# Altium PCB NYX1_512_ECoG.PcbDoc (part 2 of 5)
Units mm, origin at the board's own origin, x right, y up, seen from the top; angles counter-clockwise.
Board outline 46.64 x 13 mm, 4 copper layers (metal 2, via, metal1, electrodes), stack 0.007 mm thick; 9 components, 547 nets, 1871 pads, 0 vias.
Unrouted connection lines stored in the file: 652.
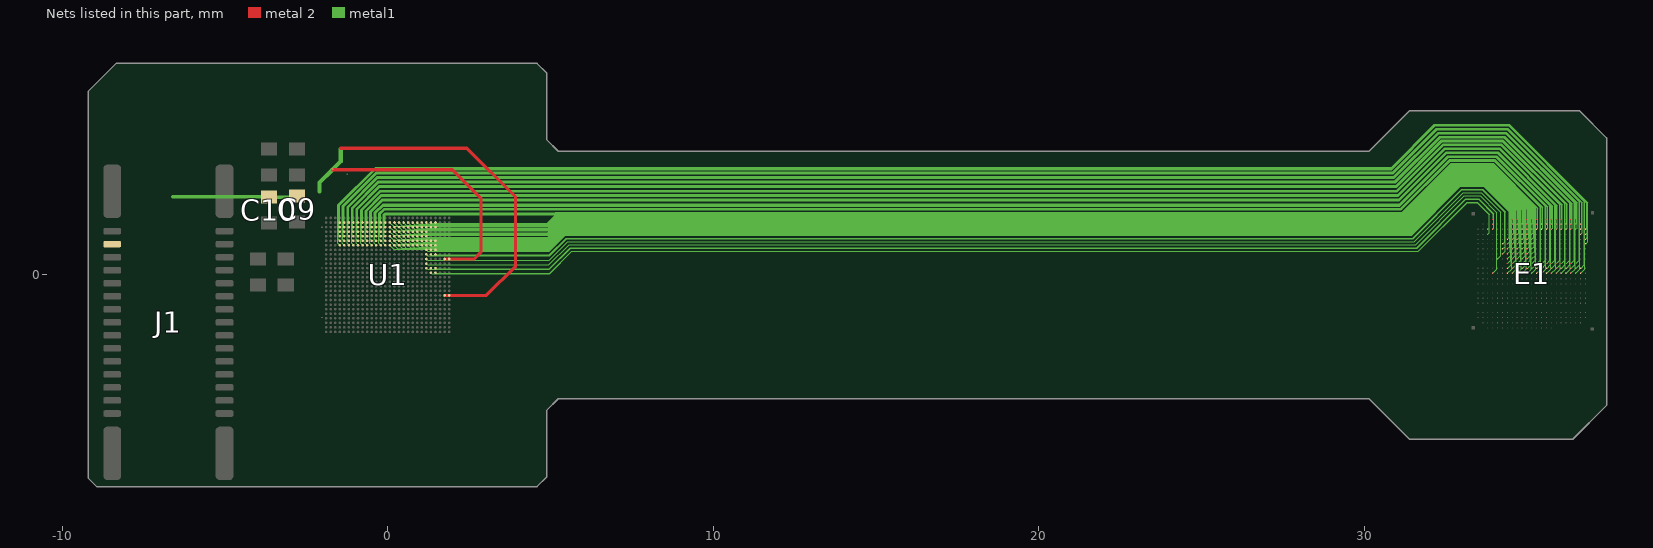
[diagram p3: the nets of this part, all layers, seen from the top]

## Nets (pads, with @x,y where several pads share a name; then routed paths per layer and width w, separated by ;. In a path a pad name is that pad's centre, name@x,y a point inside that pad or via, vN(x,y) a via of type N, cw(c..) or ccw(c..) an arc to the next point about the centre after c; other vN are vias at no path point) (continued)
DVSS_BOT: C9.2 C10.2 J1.3 pad.34@-1.423,3.873 pad.34@-1.423,3.891 pad.34@-1.423,3.909 pad.34@-1.441,3.873 pad.34@-1.441,3.891 pad.34@-1.441,3.909 pad.34@-1.459,3.873 pad.34@-1.459,3.891 pad.34@-1.459,3.909 pad.34@-1.679,3.217 pad.34@-1.679,3.235 pad.34@-1.679,3.253 pad.34@-1.697,3.217 pad.34@-1.697,3.235 pad.34@-1.697,3.253 pad.34@-1.715,3.217 pad.34@-1.715,3.235 pad.34@-1.715,3.253 U1.A10 U1.A18 U1.B10 U1.B18 | length 23.9
  metal 2 w0.1: pad.34@-1.697,3.235 pad.34@-1.679,3.235 1.99,3.235 2.866,2.359 2.866,0.696 2.661,0.491 U1.B10@1.75,0.491 ; pad.34@-1.441,3.891 pad.34@-1.423,3.891 2.433,3.891 3.929,2.395 3.929,0.264 3.036,-0.629 U1.A18@1.89,-0.629 U1.B18@1.75,-0.629
  metal1 w0.08: pad.34@-1.715,3.217 pad.34@-1.697,3.235 ; pad.34@-1.441,3.873 pad.34@-1.441,3.891
  metal1 w0.1: -6.602,2.399 -3.651,2.399 C10.2@-3.644,2.392 ; C10.2@-3.643,2.384 C9.2@-2.853,2.384 ; C9.2@-2.814,2.411 C9.2@-2.786,2.411 ; C9.2@-2.786,2.421 C9.2@-2.732,2.421 ; -2.106,2.546 -2.087,2.566
  metal1 w0.127: -2.087,2.566 -2.087,2.845 pad.34@-1.715,3.217 ; pad.34@-1.697,3.235 -1.441,3.491 pad.34@-1.441,3.873
el0: E1.190 pad.34@35.141,0.514 U1.D2 | length 36.7
  metal 2 w0.012: E1.190@35.141,0.494 pad.34@35.141,0.514
  metal1 w0.005: U1.D2@1.47,1.611 1.487,1.594 4.91,1.594 5.183,1.866 30.141,1.866 31.19,1.866 32.69,3.366 33.935,3.366 35.241,2.06 35.241,0.594 35.16,0.514 pad.34@35.141,0.514
el1: E1.212 pad.34@34.991,0.364 U1.D3 | length 36.6
  metal 2 w0.012: E1.212@34.991,0.344 pad.34@34.991,0.364
  metal1 w0.005: U1.D3@1.47,1.471 1.487,1.454 4.927,1.454 5.23,1.756 30.141,1.756 31.236,1.756 32.736,3.256 33.889,3.256 35.101,2.045 35.101,0.454 35.01,0.364 pad.34@34.991,0.364
el2: E1.95 pad.34@34.691,1.114 U1.D6 | length 35.4
  metal 2 w0.012: E1.95@34.691,1.094 pad.34@34.691,1.114
  metal1 w0.005: U1.D6@1.47,1.051 1.487,1.034 4.922,1.034 5.351,1.463 30.141,1.463 31.352,1.463 32.852,2.963 33.773,2.963 34.751,1.985 34.751,1.154 34.71,1.114 pad.34@34.691,1.114
el3: E1.117 pad.34@34.541,0.964 U1.D7 | length 35.4
  metal 2 w0.012: E1.117@34.541,0.944 pad.34@34.541,0.964
  metal1 w0.005: U1.D7@1.47,0.911 1.487,0.894 4.938,0.894 5.397,1.353 30.141,1.353 31.398,1.353 32.898,2.853 33.727,2.853 34.611,1.969 34.611,1.014 34.56,0.964 pad.34@34.541,0.964
el4: E1.167 pad.34@35.141,0.664 U1.E2 | length 36.6
  metal 2 w0.012: E1.167@35.141,0.644 pad.34@35.141,0.664
  metal1 w0.005: U1.E2@1.33,1.611 1.357,1.584 4.915,1.584 5.187,1.856 30.141,1.856 31.194,1.856 32.694,3.356 33.931,3.356 35.231,2.056 35.231,0.734 35.16,0.664 pad.34@35.141,0.664
el5: E1.189 pad.34@34.991,0.514 U1.E3 | length 36.6
  metal 2 w0.012: E1.189@34.991,0.494 pad.34@34.991,0.514
  metal1 w0.005: U1.E3@1.33,1.471 1.357,1.444 4.932,1.444 5.234,1.746 30.141,1.746 31.24,1.746 32.74,3.246 33.885,3.246 35.091,2.041 35.091,0.594 35.01,0.514 pad.34@34.991,0.514
el6: E1.72 pad.34@34.691,1.264 U1.E6 | length 35.4
  metal 2 w0.012: E1.72@34.691,1.244 pad.34@34.691,1.264
  metal1 w0.005: U1.E6@1.33,1.051 1.357,1.024 4.926,1.024 5.355,1.453 30.141,1.453 31.356,1.453 32.856,2.953 33.768,2.953 34.741,1.98 34.741,1.294 34.71,1.264 pad.34@34.691,1.264
el7: E1.94 pad.34@34.541,1.114 U1.E7 | length 35.4
  metal 2 w0.012: E1.94@34.541,1.094 pad.34@34.541,1.114
  metal1 w0.005: U1.E7@1.33,0.911 1.357,0.884 4.943,0.884 5.401,1.343 30.141,1.343 31.402,1.343 32.902,2.843 33.723,2.843 34.601,1.965 34.601,1.154 34.56,1.114 pad.34@34.541,1.114
el8: E1.144 pad.34@35.141,0.814 U1.F2 | length 36.6
  metal 2 w0.012: E1.144@35.141,0.794 pad.34@35.141,0.814
  metal1 w0.005: U1.F2@1.19,1.611 1.227,1.574 4.919,1.574 5.191,1.846 30.141,1.846 31.198,1.846 32.698,3.346 33.926,3.346 35.221,2.052 35.221,0.874 35.16,0.814 pad.34@35.141,0.814
el9: E1.166 pad.34@34.991,0.664 U1.F3 | length 36.6
  metal 2 w0.012: E1.166@34.991,0.644 pad.34@34.991,0.664
  metal1 w0.005: U1.F3@1.19,1.471 1.227,1.434 4.936,1.434 5.238,1.736 30.141,1.736 31.244,1.736 32.744,3.236 33.881,3.236 35.081,2.036 35.081,0.734 35.01,0.664 pad.34@34.991,0.664
el10: E1.234 pad.34@34.841,0.214 U1.F4 | length 36.9
  metal 2 w0.012: E1.234@34.841,0.194 pad.34@34.841,0.214
  metal1 w0.005: U1.F4@1.19,1.331 1.227,1.294 4.923,1.294 5.274,1.644 5.369,1.644 30.141,1.644 31.279,1.644 32.778,3.143 33.847,3.143 34.961,2.029 34.961,0.314 34.86,0.214 pad.34@34.841,0.214
el11: E1.28 pad.34@34.841,1.564 U1.F5 | length 35.4
  metal 2 w0.012: E1.28@34.841,1.544 pad.34@34.841,1.564
  metal1 w0.005: U1.F5@1.19,1.191 1.227,1.154 4.914,1.154 5.315,1.554 5.406,1.554 30.141,1.554 31.317,1.554 32.815,3.053 33.81,3.053 34.871,1.992 34.871,1.594 pad.34@34.841,1.564
el12: E1.49 pad.34@34.691,1.414 U1.F6 | length 35.4
  metal 2 w0.012: E1.49@34.691,1.394 pad.34@34.691,1.414
  metal1 w0.005: U1.F6@1.19,1.051 1.227,1.014 4.93,1.014 5.359,1.443 30.124,1.443 31.36,1.443 32.86,2.943 33.764,2.943 34.731,1.976 34.731,1.434 34.71,1.414 pad.34@34.691,1.414
el13: E1.71 pad.34@34.541,1.264 U1.F7 | length 35.3
  metal 2 w0.012: E1.71@34.541,1.244 pad.34@34.541,1.264
  metal1 w0.005: U1.F7@1.19,0.911 1.227,0.874 4.947,0.874 5.405,1.333 30.141,1.333 31.406,1.333 32.906,2.833 33.719,2.833 34.591,1.961 34.591,1.294 34.56,1.264 pad.34@34.541,1.264
el14: E1.121 pad.34@35.141,0.964 U1.G2 | length 36.6
  metal 2 w0.012: E1.121@35.141,0.944 pad.34@35.141,0.964
  metal1 w0.005: U1.G2@1.05,1.611 1.097,1.564 4.923,1.564 5.195,1.836 30.141,1.836 31.202,1.836 32.702,3.336 33.922,3.336 35.211,2.048 35.211,1.014 35.16,0.964 pad.34@35.141,0.964
el15: E1.143 pad.34@34.991,0.814 U1.G3 | length 36.6
  metal 2 w0.012: E1.143@34.991,0.794 pad.34@34.991,0.814
  metal1 w0.005: U1.G3@1.05,1.471 1.097,1.424 4.94,1.424 5.242,1.726 30.141,1.726 31.248,1.726 32.748,3.226 33.877,3.226 35.071,2.032 35.071,0.874 35.01,0.814 pad.34@34.991,0.814
el16: E1.211 pad.34@34.841,0.364 U1.G4 | length 36.9
  metal 2 w0.012: E1.211@34.841,0.344 pad.34@34.841,0.364
  metal1 w0.005: U1.G4@1.05,1.331 1.097,1.284 4.927,1.284 5.278,1.634 5.373,1.634 30.141,1.634 31.283,1.634 32.782,3.133 33.843,3.133 34.951,2.025 34.951,0.454 34.86,0.364 pad.34@34.841,0.364
el17: E1.8 pad.34@34.841,1.714 U1.G5 | length 35.4
  metal 2 w0.012: E1.8@34.841,1.694 pad.34@34.841,1.714
  metal1 w0.005: U1.G5@1.05,1.191 1.097,1.144 4.919,1.144 5.319,1.544 5.413,1.544 30.141,1.544 31.321,1.544 32.819,3.043 33.806,3.043 34.861,1.988 34.861,1.734 pad.34@34.841,1.714
el18: E1.27 pad.34@34.691,1.564 U1.G6 | length 35.3
  metal 2 w0.012: E1.27@34.691,1.544 pad.34@34.691,1.564
  metal1 w0.005: U1.G6@1.05,1.051 1.097,1.004 4.934,1.004 5.363,1.433 30.129,1.433 31.365,1.433 32.865,2.933 33.76,2.933 34.721,1.972 34.721,1.594 pad.34@34.691,1.564
el19: E1.48 pad.34@34.541,1.414 U1.G7 | length 35.3
  metal 2 w0.012: E1.48@34.541,1.394 pad.34@34.541,1.414
  metal1 w0.005: U1.G7@1.05,0.911 1.097,0.864 4.951,0.864 5.41,1.323 30.141,1.323 31.41,1.323 32.91,2.823 33.715,2.823 34.581,1.956 34.581,1.434 34.56,1.414 pad.34@34.541,1.414
el20: E1.98 pad.34@35.141,1.114 U1.H2 | length 36.6
  metal 2 w0.012: E1.98@35.141,1.094 pad.34@35.141,1.114
  metal1 w0.005: U1.H2@0.91,1.611 0.967,1.554 4.927,1.554 5.2,1.826 30.141,1.826 31.207,1.826 32.707,3.326 33.918,3.326 35.201,2.044 35.201,1.154 35.16,1.114 pad.34@35.141,1.114
el21: E1.120 pad.34@34.991,0.964 U1.H3 | length 36.5
  metal 2 w0.012: E1.120@34.991,0.944 pad.34@34.991,0.964
  metal1 w0.005: U1.H3@0.91,1.471 0.967,1.414 4.944,1.414 5.246,1.716 30.141,1.716 31.252,1.716 32.752,3.216 33.873,3.216 35.061,2.028 35.061,1.014 35.01,0.964 pad.34@34.991,0.964
el22: E1.188 pad.34@34.841,0.514 U1.H4 | length 36.9
  metal 2 w0.012: E1.188@34.841,0.494 pad.34@34.841,0.514
  metal1 w0.005: U1.H4@0.91,1.331 0.967,1.274 4.931,1.274 5.282,1.624 5.377,1.624 30.141,1.624 31.288,1.624 32.786,3.123 33.839,3.123 34.941,2.021 34.941,0.594 34.86,0.514 pad.34@34.841,0.514
el23: E1.256 pad.34@34.691,0.064 U1.H5 | length 37.2
  metal 2 w0.012: E1.256@34.691,0.044 pad.34@34.691,0.064
  metal1 w0.005: U1.H5@0.91,1.191 0.967,1.134 4.923,1.134 5.322,1.533 5.424,1.533 30.141,1.533 31.324,1.533 32.823,3.033 33.802,3.033 34.821,2.014 34.821,0.174 34.71,0.064 pad.34@34.691,0.064
el24: E1.7 pad.34@34.691,1.714 U1.H6 | length 35.3
  metal 2 w0.012: E1.7@34.691,1.694 pad.34@34.691,1.714
  metal1 w0.005: U1.H6@0.91,1.051 0.967,0.994 4.938,0.994 5.367,1.423 30.133,1.423 31.369,1.423 32.869,2.923 33.756,2.923 34.711,1.968 34.711,1.734 pad.34@34.691,1.714
el25: E1.26 pad.34@34.541,1.564 U1.H7 | length 35.3
  metal 2 w0.012: E1.26@34.541,1.544 pad.34@34.541,1.564
  metal1 w0.005: U1.H7@0.91,0.911 0.967,0.854 4.955,0.854 5.414,1.313 30.141,1.313 31.414,1.313 32.914,2.813 33.71,2.813 34.571,1.952 34.571,1.594 pad.34@34.541,1.564
el26: E1.75 pad.34@35.141,1.264 U1.J2 | length 36.5
  metal 2 w0.012: E1.75@35.141,1.244 pad.34@35.141,1.264
  metal1 w0.005: U1.J2@0.77,1.611 0.837,1.544 4.931,1.544 5.204,1.816 30.141,1.816 31.211,1.816 32.711,3.316 33.914,3.316 35.191,2.04 35.191,1.294 35.16,1.264 pad.34@35.141,1.264
el27: E1.97 pad.34@34.991,1.114 U1.J3 | length 36.5
  metal 2 w0.012: E1.97@34.991,1.094 pad.34@34.991,1.114
  metal1 w0.005: U1.J3@0.77,1.471 0.837,1.404 4.948,1.404 5.251,1.706 30.141,1.706 31.256,1.706 32.756,3.206 33.868,3.206 35.051,2.024 35.051,1.154 35.01,1.114 pad.34@34.991,1.114
el28: E1.165 pad.34@34.841,0.664 U1.J4 | length 36.8
  metal 2 w0.012: E1.165@34.841,0.644 pad.34@34.841,0.664
  metal1 w0.005: U1.J4@0.77,1.331 0.837,1.264 4.935,1.264 5.286,1.614 5.382,1.614 30.141,1.614 31.292,1.614 32.79,3.113 33.835,3.113 34.931,2.017 34.931,0.734 34.86,0.664 pad.34@34.841,0.664
el29: E1.233 pad.34@34.691,0.214 U1.J5 | length 37.2
  metal 2 w0.012: E1.233@34.691,0.194 pad.34@34.691,0.214
  metal1 w0.005: U1.J5@0.77,1.191 0.837,1.124 4.927,1.124 5.326,1.523 5.434,1.523 30.141,1.523 31.328,1.523 32.827,3.023 33.797,3.023 34.811,2.009 34.811,0.314 34.71,0.214 pad.34@34.691,0.214
el30: E1.255 pad.34@34.541,0.064 U1.J6 | length 37.1
  metal 2 w0.012: E1.255@34.541,0.044 pad.34@34.541,0.064
  metal1 w0.005: U1.J6@0.77,1.051 0.837,0.984 4.942,0.984 5.371,1.413 30.137,1.413 31.373,1.413 32.873,2.913 33.752,2.913 34.671,1.994 34.671,0.174 34.56,0.064 pad.34@34.541,0.064
el31: E1.6 pad.34@34.541,1.714 U1.J7 | length 35.2
  metal 2 w0.012: E1.6@34.541,1.694 pad.34@34.541,1.714
  metal1 w0.005: U1.J7@0.77,0.911 0.837,0.844 4.959,0.844 5.418,1.303 30.141,1.303 31.418,1.303 32.918,2.803 33.706,2.803 34.561,1.948 34.561,1.734 pad.34@34.541,1.714
el32: E1.52 pad.34@35.141,1.414 U1.K2 | length 36.5
  metal 2 w0.012: E1.52@35.141,1.394 pad.34@35.141,1.414
  metal1 w0.005: U1.K2@0.63,1.611 0.707,1.534 4.935,1.534 5.208,1.806 30.141,1.806 31.215,1.806 32.715,3.306 33.91,3.306 35.181,2.035 35.181,1.434 35.16,1.414 pad.34@35.141,1.414
el33: E1.74 pad.34@34.991,1.264 U1.K3 | length 36.5
  metal 2 w0.012: E1.74@34.991,1.244 pad.34@34.991,1.264
  metal1 w0.005: U1.K3@0.63,1.471 0.707,1.394 4.952,1.394 5.255,1.696 31.26,1.696 32.757,3.193 33.868,3.193 35.041,2.02 35.041,1.294 35.01,1.264 pad.34@34.991,1.264
el34: E1.142 pad.34@34.841,0.814 U1.K4 | length 36.8
  metal 2 w0.012: E1.142@34.841,0.794 pad.34@34.841,0.814
  metal1 w0.005: U1.K4@0.63,1.331 0.707,1.254 4.94,1.254 5.29,1.604 5.386,1.604 30.141,1.604 31.296,1.604 32.794,3.103 33.831,3.103 34.921,2.013 34.921,0.874 34.86,0.814 pad.34@34.841,0.814
el35: E1.210 pad.34@34.691,0.364 U1.K5 | length 37.1
  metal 2 w0.012: E1.210@34.691,0.344 pad.34@34.691,0.364
  metal1 w0.005: U1.K5@0.63,1.191 0.707,1.114 4.931,1.114 5.331,1.513 5.444,1.513 30.141,1.513 31.332,1.513 32.831,3.013 33.793,3.013 34.801,2.005 34.801,0.454 34.71,0.364 pad.34@34.691,0.364
el36: E1.232 pad.34@34.541,0.214 U1.K6 | length 37.1
  metal 2 w0.012: E1.232@34.541,0.194 pad.34@34.541,0.214
  metal1 w0.005: U1.K6@0.63,1.051 0.707,0.974 4.947,0.974 5.375,1.403 30.141,1.403 31.377,1.403 32.877,2.903 33.748,2.903 34.661,1.99 34.661,0.314 34.56,0.214 pad.34@34.541,0.214
el37: E1.254 pad.34@34.391,0.064 U1.K7 | length 37.1
  metal 2 w0.012: E1.254@34.391,0.044 pad.34@34.391,0.064
  metal1 w0.005: U1.K7@0.63,0.911 0.707,0.834 4.963,0.834 5.422,1.293 30.141,1.293 31.423,1.293 32.923,2.793 33.702,2.793 34.521,1.974 34.521,0.174 34.41,0.064 pad.34@34.391,0.064
el38: E1.30 pad.34@35.141,1.564 U1.L2 | length 36.5
  metal 2 w0.012: E1.30@35.141,1.544 pad.34@35.141,1.564
  metal1 w0.005: U1.L2@0.49,1.611 0.577,1.524 4.939,1.524 5.212,1.796 30.141,1.796 31.219,1.796 32.719,3.296 33.906,3.296 35.171,2.031 35.171,1.594 pad.34@35.141,1.564
el39: E1.51 pad.34@34.991,1.414 U1.L3 | length 36.5
  metal 2 w0.012: E1.51@34.991,1.394 pad.34@34.991,1.414
  metal1 w0.005: U1.L3@0.49,1.471 0.577,1.384 4.956,1.384 5.259,1.686 31.265,1.686 32.761,3.183 33.864,3.183 35.031,2.016 35.031,1.434 35.01,1.414 pad.34@34.991,1.414
el40: E1.119 pad.34@34.841,0.964 U1.L4 | length 36.8
  metal 2 w0.012: E1.119@34.841,0.944 pad.34@34.841,0.964
  metal1 w0.005: U1.L4@0.49,1.331 0.577,1.244 4.944,1.244 5.294,1.594 5.39,1.594 30.141,1.594 31.3,1.594 32.798,3.093 33.826,3.093 34.911,2.008 34.911,1.014 34.86,0.964 pad.34@34.841,0.964
el41: E1.187 pad.34@34.691,0.514 U1.L5 | length 37.1
  metal 2 w0.012: E1.187@34.691,0.494 pad.34@34.691,0.514
  metal1 w0.005: U1.L5@0.49,1.191 0.577,1.104 4.935,1.104 5.335,1.503 5.454,1.503 30.141,1.503 31.336,1.503 32.836,3.003 33.789,3.003 34.791,2.001 34.791,0.594 34.71,0.514 pad.34@34.691,0.514
el42: E1.209 pad.34@34.541,0.364 U1.L6 | length 37.1
  metal 2 w0.012: E1.209@34.541,0.344 pad.34@34.541,0.364
  metal1 w0.005: U1.L6@0.49,1.051 0.577,0.964 4.951,0.964 5.38,1.393 30.141,1.393 31.381,1.393 32.881,2.893 33.744,2.893 34.651,1.985 34.651,0.454 34.56,0.364 pad.34@34.541,0.364
el43: E1.231 pad.34@34.391,0.214 U1.L7 | length 37
  metal 2 w0.012: E1.231@34.391,0.194 pad.34@34.391,0.214
  metal1 w0.005: U1.L7@0.49,0.911 0.577,0.824 4.967,0.824 5.426,1.283 30.141,1.283 31.427,1.283 32.927,2.783 33.698,2.783 34.511,1.97 34.511,0.314 34.41,0.214 pad.34@34.391,0.214
el44: E1.10 pad.34@35.141,1.714 U1.M2 | length 36.4
  metal 2 w0.012: E1.10@35.141,1.694 pad.34@35.141,1.714
  metal1 w0.005: U1.M2@0.35,1.611 0.447,1.514 4.944,1.514 5.216,1.786 30.141,1.786 31.223,1.786 32.723,3.286 33.902,3.286 35.161,2.027 35.161,1.734 pad.34@35.141,1.714
el45: E1.29 pad.34@34.991,1.564 U1.M3 | length 36.4
  metal 2 w0.012: E1.29@34.991,1.544 pad.34@34.991,1.564
  metal1 w0.005: U1.M3@0.35,1.471 0.447,1.374 4.961,1.374 5.263,1.676 31.269,1.676 32.765,3.173 33.86,3.173 35.021,2.012 35.021,1.594 pad.34@34.991,1.564
el46: E1.96 pad.34@34.841,1.114 U1.M4 | length 36.7
  metal 2 w0.012: E1.96@34.841,1.094 pad.34@34.841,1.114
  metal1 w0.005: U1.M4@0.35,1.331 0.447,1.234 4.948,1.234 5.298,1.584 5.394,1.584 30.141,1.584 31.304,1.584 32.802,3.083 33.822,3.083 34.901,2.004 34.901,1.154 34.86,1.114 pad.34@34.841,1.114
el47: E1.164 pad.34@34.691,0.664 U1.M5 | length 37.1
  metal 2 w0.012: E1.164@34.691,0.644 pad.34@34.691,0.664
  metal1 w0.005: U1.M5@0.35,1.191 0.447,1.094 4.939,1.094 5.339,1.493 5.464,1.493 30.141,1.493 31.34,1.493 32.84,2.993 33.785,2.993 34.781,1.997 34.781,0.734 34.71,0.664 pad.34@34.691,0.664
el48: E1.186 pad.34@34.541,0.514 U1.M6 | length 37
  metal 2 w0.012: E1.186@34.541,0.494 pad.34@34.541,0.514
  metal1 w0.005: U1.M6@0.35,1.051 0.447,0.954 4.955,0.954 5.384,1.383 30.141,1.383 31.385,1.383 32.885,2.883 33.739,2.883 34.641,1.981 34.641,0.594 34.56,0.514 pad.34@34.541,0.514
el49: E1.208 pad.34@34.391,0.364 U1.M7 | length 37
  metal 2 w0.012: E1.208@34.391,0.344 pad.34@34.391,0.364
  metal1 w0.005: U1.M7@0.35,0.911 0.447,0.814 4.972,0.814 5.43,1.273 30.141,1.273 31.431,1.273 32.931,2.773 33.694,2.773 34.501,1.966 34.501,0.454 34.41,0.364 pad.34@34.391,0.364
el50: E1.258 pad.34@34.991,0.064 U1.N2 | length 38.3
  metal 2 w0.012: E1.258@34.991,0.044 pad.34@34.991,0.064
  metal1 w0.005: U1.N2@0.21,1.611 0.317,1.504 4.948,1.504 5.22,1.776 30.141,1.776 31.227,1.776 32.727,3.276 33.897,3.276 35.121,2.053 35.121,0.174 35.01,0.064 pad.34@34.991,0.064
el51: E1.9 pad.34@34.991,1.714 U1.N3 | length 36.4
  metal 2 w0.012: E1.9@34.991,1.694 pad.34@34.991,1.714
  metal1 w0.005: U1.N3@0.21,1.471 0.317,1.364 4.965,1.364 5.267,1.666 31.273,1.666 32.769,3.163 33.855,3.163 35.011,2.007 35.011,1.734 pad.34@34.991,1.714
el52: E1.73 pad.34@34.841,1.264 U1.N4 | length 36.7
  metal 2 w0.012: E1.73@34.841,1.244 pad.34@34.841,1.264
  metal1 w0.005: U1.N4@0.21,1.331 0.317,1.224 4.952,1.224 5.303,1.574 5.398,1.574 30.141,1.574 31.308,1.574 32.807,3.073 33.818,3.073 34.891,2 34.891,1.294 34.86,1.264 pad.34@34.841,1.264
el53: E1.141 pad.34@34.691,0.814 U1.N5 | length 37
  metal 2 w0.012: E1.141@34.691,0.794 pad.34@34.691,0.814
  metal1 w0.005: U1.N5@0.21,1.191 0.317,1.084 4.943,1.084 5.343,1.483 5.474,1.483 30.141,1.483 31.345,1.483 32.844,2.983 33.781,2.983 34.771,1.993 34.771,0.874 34.71,0.814 pad.34@34.691,0.814
el54: E1.163 pad.34@34.541,0.664 U1.N6 | length 37
  metal 2 w0.012: E1.163@34.541,0.644 pad.34@34.541,0.664
  metal1 w0.005: U1.N6@0.21,1.051 0.317,0.944 4.959,0.944 5.388,1.373 30.141,1.373 31.389,1.373 32.889,2.873 33.735,2.873 34.631,1.977 34.631,0.734 34.56,0.664 pad.34@34.541,0.664
el55: E1.185 pad.34@34.391,0.514 U1.N7 | length 37
  metal 2 w0.012: E1.185@34.391,0.494 pad.34@34.391,0.514
  metal1 w0.005: U1.N7@0.21,0.911 0.317,0.804 4.976,0.804 5.434,1.263 30.141,1.263 31.435,1.263 32.935,2.763 33.69,2.763 34.491,1.962 34.491,0.594 34.41,0.514 pad.34@34.391,0.514
el56: E1.235 pad.34@34.991,0.214 U1.P2 | length 38.2
  metal 2 w0.012: E1.235@34.991,0.194 pad.34@34.991,0.214
  metal1 w0.005: U1.P2@0.07,1.611 0.188,1.494 4.952,1.494 5.224,1.766 30.141,1.766 31.231,1.766 32.731,3.266 33.893,3.266 35.111,2.049 35.111,0.314 35.01,0.214 pad.34@34.991,0.214
el57: E1.257 pad.34@34.841,0.064 U1.P3 | length 38.2
  metal 2 w0.012: E1.257@34.841,0.044 pad.34@34.841,0.064
  metal1 w0.005: U1.P3@0.07,1.471 0.188,1.354 4.969,1.354 5.269,1.654 5.365,1.654 30.137,1.654 31.275,1.654 32.773,3.153 33.851,3.153 34.971,2.033 34.971,0.174 34.86,0.064 pad.34@34.841,0.064
el58: E1.50 pad.34@34.841,1.414 U1.P4 | length 36.7
  metal 2 w0.012: E1.50@34.841,1.394 pad.34@34.841,1.414
  metal1 w0.005: U1.P4@0.07,1.331 0.188,1.214 4.956,1.214 5.307,1.564 5.402,1.564 30.141,1.564 31.312,1.564 32.811,3.063 33.814,3.063 34.881,1.996 34.881,1.434 34.86,1.414 pad.34@34.841,1.414
el59: E1.118 pad.34@34.691,0.964 U1.P5 | length 37
  metal 2 w0.012: E1.118@34.691,0.944 pad.34@34.691,0.964
  metal1 w0.005: U1.P5@0.07,1.191 0.188,1.074 4.948,1.074 5.347,1.473 30.141,1.473 31.349,1.473 32.848,2.973 33.777,2.973 34.761,1.989 34.761,1.014 34.71,0.964 pad.34@34.691,0.964
el60: E1.140 pad.34@34.541,0.814 U1.P6 | length 37
  metal 2 w0.012: E1.140@34.541,0.794 pad.34@34.541,0.814
  metal1 w0.005: U1.P6@0.07,1.051 0.188,0.934 4.963,0.934 5.392,1.363 30.141,1.363 31.394,1.363 32.894,2.863 33.731,2.863 34.621,1.973 34.621,0.874 34.56,0.814 pad.34@34.541,0.814
el61: E1.162 pad.34@34.391,0.664 U1.P7 | length 37
  metal 2 w0.012: E1.162@34.391,0.644 pad.34@34.391,0.664
  metal1 w0.005: U1.P7@0.07,0.911 0.188,0.794 4.98,0.794 5.439,1.253 30.141,1.253 31.439,1.253 32.939,2.753 33.686,2.753 34.481,1.957 34.481,0.734 34.41,0.664 pad.34@34.391,0.664
el62: E1.213 pad.34@35.141,0.364 U1.R2 | length 38.5
  metal 2 w0.012: E1.213@35.141,0.344 pad.34@35.141,0.364
  metal1 w0.005: U1.R2@-0.07,1.611 -0.07,1.844 -0.058,1.856 5.159,1.856 5.179,1.876 30.141,1.876 31.186,1.876 32.686,3.376 33.939,3.376 35.251,2.064 35.251,0.454 35.16,0.364 pad.34@35.141,0.364
el63: E1.236 pad.34@35.141,0.214 U1.R3 | length 38.8
  metal 2 w0.012: E1.236@35.141,0.194 pad.34@35.141,0.214
  metal1 w0.005: U1.R3@-0.07,1.471 -0.088,1.489 -0.088,1.844 -0.058,1.874 5.161,1.874 5.173,1.886 30.141,1.886 31.182,1.886 32.682,3.386 33.943,3.386 35.261,2.069 35.261,0.314 35.16,0.214 pad.34@35.141,0.214
el64: E1.259 pad.34@35.141,0.064 U1.R4 | length 39.2
  metal 2 w0.012: E1.259@35.141,0.044 pad.34@35.141,0.064
  metal1 w0.005: U1.R4@-0.07,1.331 -0.098,1.359 -0.098,1.849 -0.062,1.884 5.157,1.884 5.169,1.896 30.141,1.896 31.178,1.896 32.678,3.396 33.947,3.396 35.271,2.073 35.271,0.174 35.16,0.064 pad.34@35.141,0.064
el65: E1.11 pad.34@35.291,1.714 U1.R5 | length 37.7
  metal 2 w0.012: E1.11@35.291,1.694 pad.34@35.291,1.714
  metal1 w0.005: U1.R5@-0.07,1.191 -0.108,1.229 -0.108,1.853 -0.066,1.894 5.153,1.894 5.165,1.906 30.141,1.906 31.173,1.906 32.673,3.406 33.951,3.406 35.311,2.047 35.311,1.734 pad.34@35.291,1.714
el66: E1.31 pad.34@35.291,1.564 U1.R6 | length 38
  metal 2 w0.012: E1.31@35.291,1.544 pad.34@35.291,1.564
  metal1 w0.005: U1.R6@-0.07,1.051 -0.118,1.099 -0.118,1.857 -0.07,1.904 5.149,1.904 5.161,1.916 30.141,1.916 31.169,1.916 32.669,3.416 33.955,3.416 35.321,2.051 35.321,1.594 pad.34@35.291,1.564
el67: E1.53 pad.34@35.291,1.414 U1.R7 | length 38.3
  metal 2 w0.012: E1.53@35.291,1.394 pad.34@35.291,1.414
  metal1 w0.005: U1.R7@-0.07,0.911 -0.128,0.969 -0.128,1.861 -0.075,1.914 5.144,1.914 5.157,1.926 30.141,1.926 31.165,1.926 32.665,3.426 33.96,3.426 35.331,2.055 35.331,1.434 35.31,1.414 pad.34@35.291,1.414
el68: E1.214 pad.34@35.291,0.364 U1.T2 | length 38.9
  metal 2 w0.012: E1.214@35.291,0.344 pad.34@35.291,0.364
  metal1 w0.005: U1.T2@-0.21,1.611 -0.21,1.878 -0.091,1.996 31.136,1.996 32.636,3.496 33.989,3.496 35.401,2.084 35.401,0.454 35.31,0.364 pad.34@35.291,0.364
el69: E1.237 pad.34@35.291,0.214 U1.T3 | length 39.3
  metal 2 w0.012: E1.237@35.291,0.194 pad.34@35.291,0.214
  metal1 w0.005: U1.T3@-0.21,1.471 -0.228,1.489 -0.228,1.874 -0.094,2.007 30.141,2.007 31.133,2.007 32.633,3.507 33.992,3.507 35.411,2.088 35.411,0.314 35.31,0.214 pad.34@35.291,0.214
el70: E1.260 pad.34@35.291,0.064 U1.T4 | length 39.6
  metal 2 w0.012: E1.260@35.291,0.044 pad.34@35.291,0.064
  metal1 w0.005: U1.T4@-0.21,1.331 -0.238,1.359 -0.238,1.878 -0.098,2.017 30.141,2.017 31.129,2.017 32.629,3.517 33.996,3.517 35.421,2.092 35.421,0.174 35.31,0.064 pad.34@35.291,0.064
el71: E1.12 pad.34@35.441,1.714 U1.T5 | length 38.1
  metal 2 w0.012: E1.12@35.441,1.694 pad.34@35.441,1.714
  metal1 w0.005: U1.T5@-0.21,1.191 -0.248,1.229 -0.248,1.882 -0.103,2.027 30.141,2.027 31.125,2.027 32.625,3.527 34,3.527 35.461,2.067 35.461,1.734 pad.34@35.441,1.714
el72: E1.32 pad.34@35.441,1.564 U1.T6 | length 38.4
  metal 2 w0.012: E1.32@35.441,1.544 pad.34@35.441,1.564
  metal1 w0.005: U1.T6@-0.21,1.051 -0.258,1.099 -0.258,1.887 -0.107,2.037 30.141,2.037 31.121,2.037 32.62,3.537 34.004,3.537 35.471,2.071 35.471,1.594 pad.34@35.441,1.564
el73: E1.54 pad.34@35.441,1.414 U1.T7 | length 38.8
  metal 2 w0.012: E1.54@35.441,1.394 pad.34@35.441,1.414
  metal1 w0.005: U1.T7@-0.21,0.911 -0.268,0.969 -0.268,1.891 -0.111,2.047 30.141,2.047 31.116,2.047 32.616,3.547 34.008,3.547 35.481,2.075 35.481,1.434 35.46,1.414 pad.34@35.441,1.414
el74: E1.215 pad.34@35.441,0.364 U1.U2 | length 39.3
  metal 2 w0.012: E1.215@35.441,0.344 pad.34@35.441,0.364
  metal1 w0.005: U1.U2@-0.35,1.611 -0.35,1.907 -0.14,2.117 30.141,2.117 31.087,2.117 32.587,3.617 34.037,3.617 35.551,2.104 35.551,0.454 35.46,0.364 pad.34@35.441,0.364
el75: E1.238 pad.34@35.441,0.214 U1.U3 | length 39.7
  metal 2 w0.012: E1.238@35.441,0.194 pad.34@35.441,0.214
  metal1 w0.005: U1.U3@-0.35,1.471 -0.368,1.489 -0.368,1.904 -0.144,2.127 30.141,2.127 31.083,2.127 32.583,3.627 34.042,3.627 35.561,2.108 35.561,0.314 35.46,0.214 pad.34@35.441,0.214
el76: E1.261 pad.34@35.441,0.064 U1.U4 | length 40
  metal 2 w0.012: E1.261@35.441,0.044 pad.34@35.441,0.064
  metal1 w0.005: U1.U4@-0.35,1.331 -0.378,1.359 -0.378,1.908 -0.148,2.137 30.141,2.137 31.079,2.137 32.579,3.637 34.046,3.637 35.571,2.112 35.571,0.174 35.46,0.064 pad.34@35.441,0.064
el77: E1.13 pad.34@35.591,1.714 U1.U5 | length 38.5
  metal 2 w0.012: E1.13@35.591,1.694 pad.34@35.591,1.714
  metal1 w0.005: U1.U5@-0.35,1.191 -0.388,1.229 -0.388,1.912 -0.126,2.174 30.141,2.174 31.102,2.174 32.575,3.647 34.05,3.647 35.611,2.086 35.611,1.734 pad.34@35.591,1.714
el78: E1.33 pad.34@35.591,1.564 U1.U6 | length 38.8
  metal 2 w0.012: E1.33@35.591,1.544 pad.34@35.591,1.564
  metal1 w0.005: U1.U6@-0.35,1.051 -0.398,1.099 -0.398,1.916 -0.13,2.184 31.097,2.184 32.571,3.657 34.054,3.657 35.621,2.091 35.621,1.594 pad.34@35.591,1.564
el79: E1.55 pad.34@35.591,1.414 U1.U7 | length 39.2
  metal 2 w0.012: E1.55@35.591,1.394 pad.34@35.591,1.414
  metal1 w0.005: U1.U7@-0.35,0.911 -0.408,0.969 -0.408,1.92 -0.134,2.194 31.093,2.194 32.567,3.667 34.058,3.667 35.631,2.095 35.631,1.434 35.61,1.414 pad.34@35.591,1.414
el80: E1.216 pad.34@35.591,0.364 U1.V2 | length 39.8
  metal 2 w0.012: E1.216@35.591,0.344 pad.34@35.591,0.364
  metal1 w0.005: U1.V2@-0.49,1.611 -0.49,1.937 -0.151,2.276 30.141,2.276 31.077,2.276 32.538,3.737 34.087,3.737 35.701,2.124 35.701,0.454 35.61,0.364 pad.34@35.591,0.364
el81: E1.239 pad.34@35.591,0.214 U1.V3 | length 40.1
  metal 2 w0.012: E1.239@35.591,0.194 pad.34@35.591,0.214
  metal1 w0.005: U1.V3@-0.49,1.471 -0.508,1.489 -0.508,1.934 -0.147,2.294 30.141,2.294 31.08,2.294 32.533,3.747 34.091,3.747 35.711,2.128 35.711,0.314 35.61,0.214 pad.34@35.591,0.214
el82: E1.262 pad.34@35.591,0.064 U1.V4 | length 40.4
  metal 2 w0.012: E1.262@35.591,0.044 pad.34@35.591,0.064
  metal1 w0.005: U1.V4@-0.49,1.331 -0.518,1.359 -0.518,1.938 -0.151,2.304 30.141,2.304 31.076,2.304 32.529,3.757 34.095,3.757 35.721,2.132 35.721,0.174 35.61,0.064 pad.34@35.591,0.064
el83: E1.14 pad.34@35.741,1.714 U1.V5 | length 38.9
  metal 2 w0.012: E1.14@35.741,1.694 pad.34@35.741,1.714
  metal1 w0.005: U1.V5@-0.49,1.191 -0.528,1.229 -0.528,1.942 -0.156,2.314 30.141,2.314 31.072,2.314 32.525,3.767 34.1,3.767 35.761,2.106 35.761,1.734 pad.34@35.741,1.714
el84: E1.34 pad.34@35.741,1.564 U1.V6 | length 39.2
  metal 2 w0.012: E1.34@35.741,1.544 pad.34@35.741,1.564
  metal1 w0.005: U1.V6@-0.49,1.051 -0.538,1.099 -0.538,1.946 -0.16,2.324 30.141,2.324 31.068,2.324 32.521,3.777 34.104,3.777 35.771,2.11 35.771,1.594 pad.34@35.741,1.564
el85: E1.56 pad.34@35.741,1.414 U1.V7 | length 39.6
  metal 2 w0.012: E1.56@35.741,1.394 pad.34@35.741,1.414
  metal1 w0.005: U1.V7@-0.49,0.911 -0.548,0.969 -0.548,1.95 -0.164,2.334 30.141,2.334 31.063,2.334 32.517,3.787 34.108,3.787 35.781,2.114 35.781,1.434 35.76,1.414 pad.34@35.741,1.414
el86: E1.217 pad.34@35.741,0.364 U1.W2 | length 40.2
  metal 2 w0.012: E1.217@35.741,0.344 pad.34@35.741,0.364
  metal1 w0.005: U1.W2@-0.63,1.611 -0.63,1.967 -0.18,2.416 30.141,2.416 31.047,2.416 32.488,3.857 34.137,3.857 35.851,2.143 35.851,0.454 35.76,0.364 pad.34@35.741,0.364
el87: E1.240 pad.34@35.741,0.214 U1.W3 | length 40.5
  metal 2 w0.012: E1.240@35.741,0.194 pad.34@35.741,0.214
  metal1 w0.005: U1.W3@-0.63,1.471 -0.648,1.489 -0.648,1.963 -0.177,2.434 30.141,2.434 31.05,2.434 32.484,3.867 34.141,3.867 35.861,2.148 35.861,0.314 35.76,0.214 pad.34@35.741,0.214
el88: E1.263 pad.34@35.741,0.064 U1.W4 | length 40.9
  metal 2 w0.012: E1.263@35.741,0.044 pad.34@35.741,0.064
  metal1 w0.005: U1.W4@-0.63,1.331 -0.658,1.359 -0.658,1.968 -0.181,2.444 30.141,2.444 31.046,2.444 32.48,3.877 34.145,3.877 35.871,2.152 35.871,0.174 35.76,0.064 pad.34@35.741,0.064
el89: E1.15 pad.34@35.891,1.714 U1.W5 | length 39.3
  metal 2 w0.012: E1.15@35.891,1.694 pad.34@35.891,1.714
  metal1 w0.005: U1.W5@-0.63,1.191 -0.668,1.229 -0.668,1.972 -0.185,2.454 30.141,2.454 31.042,2.454 32.475,3.887 34.149,3.887 35.911,2.126 35.911,1.734 pad.34@35.891,1.714
el90: E1.35 pad.34@35.891,1.564 U1.W6 | length 39.7
  metal 2 w0.012: E1.35@35.891,1.544 pad.34@35.891,1.564
  metal1 w0.005: U1.W6@-0.63,1.051 -0.678,1.099 -0.678,1.976 -0.189,2.464 30.141,2.464 31.038,2.464 32.471,3.897 34.153,3.897 35.921,2.13 35.921,1.594 pad.34@35.891,1.564
el91: E1.57 pad.34@35.891,1.414 U1.W7 | length 40
  metal 2 w0.012: E1.57@35.891,1.394 pad.34@35.891,1.414
  metal1 w0.005: U1.W7@-0.63,0.911 -0.688,0.969 -0.688,1.98 -0.194,2.474 30.141,2.474 31.034,2.474 32.467,3.907 34.158,3.907 35.931,2.134 35.931,1.434 35.91,1.414 pad.34@35.891,1.414
el92: E1.218 pad.34@35.891,0.364 U1.Y2 | length 40.6
  metal 2 w0.012: E1.218@35.891,0.344 pad.34@35.891,0.364
  metal1 w0.005: U1.Y2@-0.77,1.611 -0.77,1.997 -0.212,2.554 30.141,2.554 31.015,2.554 32.438,3.977 34.187,3.977 36.001,2.163 36.001,0.454 35.91,0.364 pad.34@35.891,0.364
el93: E1.241 pad.34@35.891,0.214 U1.Y3 | length 40.9
  metal 2 w0.012: E1.241@35.891,0.194 pad.34@35.891,0.214
  metal1 w0.005: U1.Y3@-0.77,1.471 -0.788,1.489 -0.788,1.993 -0.216,2.564 30.141,2.564 31.011,2.564 32.434,3.987 34.191,3.987 36.011,2.167 36.011,0.314 35.91,0.214 pad.34@35.891,0.214
el94: E1.264 pad.34@35.891,0.064 U1.Y4 | length 41.3
  metal 2 w0.012: E1.264@35.891,0.044 pad.34@35.891,0.064
  metal1 w0.005: U1.Y4@-0.77,1.331 -0.798,1.359 -0.798,1.997 -0.22,2.574 30.141,2.574 31.007,2.574 32.43,3.997 34.195,3.997 36.021,2.171 36.021,0.174 35.91,0.064 pad.34@35.891,0.064
el95: E1.16 pad.34@36.041,1.714 U1.Y5 | length 39.8
  metal 2 w0.012: E1.16@36.041,1.694 pad.34@36.041,1.714
  metal1 w0.005: U1.Y5@-0.77,1.191 -0.808,1.229 -0.808,2.001 -0.225,2.584 30.141,2.584 31.003,2.584 32.425,4.007 34.199,4.007 36.061,2.146 36.061,1.734 pad.34@36.041,1.714
el96: E1.36 pad.34@36.041,1.564 U1.Y6 | length 40.1
  metal 2 w0.012: E1.36@36.041,1.544 pad.34@36.041,1.564
  metal1 w0.005: U1.Y6@-0.77,1.051 -0.818,1.099 -0.818,2.006 -0.229,2.594 30.141,2.594 30.998,2.594 32.421,4.017 34.203,4.017 36.071,2.15 36.071,1.594 pad.34@36.041,1.564
el97: E1.58 pad.34@36.041,1.414 U1.Y7 | length 40.4
  metal 2 w0.012: E1.58@36.041,1.394 pad.34@36.041,1.414
  metal1 w0.005: U1.Y7@-0.77,0.911 -0.828,0.969 -0.828,2.01 -0.233,2.604 30.141,2.604 30.994,2.604 32.417,4.027 34.207,4.027 36.081,2.154 36.081,1.434 36.06,1.414 pad.34@36.041,1.414
el98: E1.219 pad.34@36.041,0.364 U1.AA2 | length 41
  metal 2 w0.012: E1.219@36.041,0.344 pad.34@36.041,0.364
  metal1 w0.005: U1.AA2@-0.91,1.611 -0.91,2.026 -0.24,2.696 30.141,2.696 30.987,2.696 32.388,4.097 34.236,4.097 36.151,2.183 36.151,0.454 36.06,0.364 pad.34@36.041,0.364
el99: E1.242 pad.34@36.041,0.214 U1.AA3 | length 41.4
  metal 2 w0.012: E1.242@36.041,0.194 pad.34@36.041,0.214
  metal1 w0.005: U1.AA3@-0.91,1.471 -0.928,1.489 -0.928,2.023 -0.236,2.714 30.141,2.714 30.991,2.714 32.384,4.107 34.24,4.107 36.161,2.187 36.161,0.314 36.06,0.214 pad.34@36.041,0.214
el100: E1.265 pad.34@36.041,0.064 U1.AA4 | length 41.7
  metal 2 w0.012: E1.265@36.041,0.044 pad.34@36.041,0.064
  metal1 w0.005: U1.AA4@-0.91,1.331 -0.938,1.359 -0.938,2.027 -0.241,2.724 30.141,2.724 30.986,2.724 32.38,4.117 34.245,4.117 36.171,2.191 36.171,0.174 36.06,0.064 pad.34@36.041,0.064
el101: E1.17 pad.34@36.191,1.714 U1.AA5 | length 40.2
  metal 2 w0.012: E1.17@36.191,1.694 pad.34@36.191,1.714
  metal1 w0.005: U1.AA5@-0.91,1.191 -0.948,1.229 -0.948,2.031 -0.245,2.734 30.141,2.734 30.982,2.734 32.376,4.127 34.249,4.127 36.211,2.165 36.211,1.734 pad.34@36.191,1.714
el102: E1.37 pad.34@36.191,1.564 U1.AA6 | length 40.5
  metal 2 w0.012: E1.37@36.191,1.544 pad.34@36.191,1.564
  metal1 w0.005: U1.AA6@-0.91,1.051 -0.958,1.099 -0.958,2.035 -0.249,2.744 30.141,2.744 30.978,2.744 32.372,4.137 34.253,4.137 36.221,2.17 36.221,1.594 pad.34@36.191,1.564
el103: E1.59 pad.34@36.191,1.414 U1.AA7 | length 40.8
  metal 2 w0.012: E1.59@36.191,1.394 pad.34@36.191,1.414
  metal1 w0.005: U1.AA7@-0.91,0.911 -0.968,0.969 -0.968,2.039 -0.253,2.754 30.141,2.754 30.974,2.754 32.367,4.147 34.257,4.147 36.231,2.174 36.231,1.434 36.21,1.414 pad.34@36.191,1.414
el104: E1.220 pad.34@36.191,0.364 U1.AB2 | length 41.4
  metal 2 w0.012: E1.220@36.191,0.344 pad.34@36.191,0.364
  metal1 w0.005: U1.AB2@-1.05,1.611 -1.05,2.056 -0.27,2.836 30.957,2.836 32.338,4.217 34.286,4.217 36.301,2.203 36.301,0.454 36.21,0.364 pad.34@36.191,0.364
el105: E1.243 pad.34@36.191,0.214 U1.AB3 | length 41.8
  metal 2 w0.012: E1.243@36.191,0.194 pad.34@36.191,0.214
  metal1 w0.005: U1.AB3@-1.05,1.471 -1.068,1.489 -1.068,2.053 -0.266,2.854 30.141,2.854 30.951,2.854 32.325,4.227 34.29,4.227 36.311,2.207 36.311,0.314 36.21,0.214 pad.34@36.191,0.214
el106: E1.266 pad.34@36.191,0.064 U1.AB4 | length 42.1
  metal 2 w0.012: E1.266@36.191,0.044 pad.34@36.191,0.064
  metal1 w0.005: U1.AB4@-1.05,1.331 -1.078,1.359 -1.078,2.057 -0.27,2.864 30.141,2.864 30.947,2.864 32.321,4.237 34.294,4.237 36.321,2.211 36.321,0.174 36.21,0.064 pad.34@36.191,0.064
el107: E1.18 pad.34@36.341,1.714 U1.AB5 | length 40.6
  metal 2 w0.012: E1.18@36.341,1.694 pad.34@36.341,1.714
  metal1 w0.005: U1.AB5@-1.05,1.191 -1.088,1.229 -1.088,2.061 -0.275,2.874 30.141,2.874 30.943,2.874 32.317,4.247 34.298,4.247 36.361,2.185 36.361,1.734 pad.34@36.341,1.714
el108: E1.38 pad.34@36.341,1.564 U1.AB6 | length 40.9
  metal 2 w0.012: E1.38@36.341,1.544 pad.34@36.341,1.564
  metal1 w0.005: U1.AB6@-1.05,1.051 -1.098,1.099 -1.098,2.065 -0.279,2.884 30.141,2.884 30.939,2.884 32.313,4.257 34.303,4.257 36.371,2.189 36.371,1.594 pad.34@36.341,1.564
el109: E1.60 pad.34@36.341,1.414 U1.AB7 | length 41.3
  metal 2 w0.012: E1.60@36.341,1.394 pad.34@36.341,1.414
  metal1 w0.005: U1.AB7@-1.05,0.911 -1.108,0.969 -1.108,2.069 -0.283,2.894 30.141,2.894 30.935,2.894 32.308,4.267 34.307,4.267 36.381,2.193 36.381,1.434 36.36,1.414 pad.34@36.341,1.414
el110: E1.221 pad.34@36.341,0.364 U1.AC2 | length 41.9
  metal 2 w0.012: E1.221@36.341,0.344 pad.34@36.341,0.364
  metal1 w0.005: U1.AC2@-1.19,1.611 -1.19,2.086 -0.302,2.974 30.916,2.974 32.279,4.337 34.336,4.337 36.451,2.222 36.451,0.454 36.36,0.364 pad.34@36.341,0.364
el111: E1.244 pad.34@36.341,0.214 U1.AC3 | length 42.2
  metal 2 w0.012: E1.244@36.341,0.194 pad.34@36.341,0.214
  metal1 w0.005: U1.AC3@-1.19,1.471 -1.208,1.489 -1.208,2.082 -0.306,2.984 30.912,2.984 32.275,4.347 34.34,4.347 36.461,2.227 36.461,0.314 36.36,0.214 pad.34@36.341,0.214
el112: E1.267 pad.34@36.341,0.064 U1.AC4 | length 42.5
  metal 2 w0.012: E1.267@36.341,0.044 pad.34@36.341,0.064
  metal1 w0.005: U1.AC4@-1.19,1.331 -1.218,1.359 -1.218,2.087 -0.31,2.994 30.908,2.994 32.271,4.357 34.344,4.357 36.471,2.231 36.471,0.174 36.36,0.064 pad.34@36.341,0.064
el113: E1.19 pad.34@36.491,1.714 U1.AC5 | length 41
  metal 2 w0.012: E1.19@36.491,1.694 pad.34@36.491,1.714
  metal1 w0.005: U1.AC5@-1.19,1.191 -1.228,1.229 -1.228,2.091 -0.304,3.014 30.913,3.014 32.267,4.367 34.348,4.367 36.511,2.205 36.511,1.734 pad.34@36.491,1.714
el114: E1.39 pad.34@36.491,1.564 U1.AC6 | length 41.3
  metal 2 w0.012: E1.39@36.491,1.544 pad.34@36.491,1.564
  metal1 w0.005: U1.AC6@-1.19,1.051 -1.238,1.099 -1.238,2.095 -0.308,3.024 0.437,3.024 30.108,3.024 30.909,3.024 32.263,4.377 34.352,4.377 36.521,2.209 36.521,1.594 pad.34@36.491,1.564
el115: E1.61 pad.34@36.491,1.414 U1.AC7 | length 41.7
  metal 2 w0.012: E1.61@36.491,1.394 pad.34@36.491,1.414
  metal1 w0.005: U1.AC7@-1.19,0.911 -1.248,0.969 -1.248,2.099 -0.313,3.034 0.437,3.034 30.141,3.034 30.905,3.034 32.262,4.39 34.354,4.39 36.531,2.213 36.531,1.434 36.51,1.414 pad.34@36.491,1.414
el116: E1.222 pad.34@36.491,0.364 U1.AD2 | length 42.3
  metal 2 w0.012: E1.222@36.491,0.344 pad.34@36.491,0.364
  metal1 w0.005: U1.AD2@-1.33,1.611 -1.33,2.115 -0.329,3.116 30.141,3.116 30.889,3.116 32.233,4.46 34.383,4.46 36.601,2.242 36.601,0.454 36.51,0.364 pad.34@36.491,0.364
el117: E1.245 pad.34@36.491,0.214 U1.AD3 | length 42.6
  metal 2 w0.012: E1.245@36.491,0.194 pad.34@36.491,0.214
  metal1 w0.005: U1.AD3@-1.33,1.471 -1.35,1.491 -1.35,2.11 -0.331,3.128 30.141,3.128 30.886,3.128 32.228,4.47 34.387,4.47 36.611,2.246 36.611,0.314 36.51,0.214 pad.34@36.491,0.214
el118: E1.268 pad.34@36.491,0.064 U1.AD4 | length 43
  metal 2 w0.012: E1.268@36.491,0.044 pad.34@36.491,0.064
  metal1 w0.005: U1.AD4@-1.33,1.331 -1.358,1.359 -1.358,1.485 -1.36,1.487 -1.36,2.114 -0.335,3.138 30.141,3.138 30.882,3.138 32.224,4.48 34.391,4.48 36.621,2.25 36.621,0.174 36.51,0.064 pad.34@36.491,0.064
el119: E1.40 pad.34@36.641,1.564 U1.AD5 | length 41.6
  metal 2 w0.012: E1.40@36.641,1.544 pad.34@36.641,1.564
  metal1 w0.005: U1.AD5@-1.33,1.191 -1.368,1.229 -1.368,1.481 -1.37,1.483 -1.37,2.118 -0.34,3.148 30.141,3.148 30.878,3.148 32.22,4.49 34.395,4.49 36.671,2.215 36.671,1.594 pad.34@36.641,1.564
el120: E1.62 pad.34@36.641,1.414 U1.AD6 | length 41.9
  metal 2 w0.012: E1.62@36.641,1.394 pad.34@36.641,1.414
  metal1 w0.005: U1.AD6@-1.33,1.051 -1.378,1.099 -1.378,1.477 -1.38,1.479 -1.38,2.123 -0.344,3.158 30.141,3.158 30.874,3.158 32.216,4.5 34.399,4.5 36.681,2.219 36.681,1.434 36.66,1.414 pad.34@36.641,1.414
el121: E1.85 pad.34@36.641,1.264 U1.AD7 | length 42.3
  metal 2 w0.012: E1.85@36.641,1.244 pad.34@36.641,1.264
  metal1 w0.005: U1.AD7@-1.33,0.911 -1.388,0.969 -1.388,1.472 -1.39,1.474 -1.39,2.127 -0.348,3.168 30.141,3.168 30.87,3.168 32.212,4.51 34.403,4.51 36.691,2.223 36.691,1.294 36.66,1.264 pad.34@36.641,1.264
el122: E1.246 pad.34@36.641,0.214 U1.AE2 | length 42.9
  metal 2 w0.012: E1.246@36.641,0.194 pad.34@36.641,0.214
  metal1 w0.005: U1.AE2@-1.47,1.611 -1.47,2.145 -0.377,3.238 30.841,3.238 32.183,4.58 34.432,4.58 36.761,2.252 36.761,0.314 36.66,0.214 pad.34@36.641,0.214
el123: E1.269 pad.34@36.641,0.064 U1.AE3 | length 43.2
  metal 2 w0.012: E1.269@36.641,0.044 pad.34@36.641,0.064
  metal1 w0.005: U1.AE3@-1.47,1.471 -1.488,1.489 -1.488,2.142 -0.381,3.248 30.837,3.248 32.179,4.59 34.436,4.59 36.771,2.256 36.771,0.174 36.66,0.064 pad.34@36.641,0.064
el124: E1.63 pad.34@36.791,1.414 U1.AE4 | length 42
  metal 2 w0.012: E1.63@36.791,1.394 pad.34@36.791,1.414
  metal1 w0.005: U1.AE4@-1.47,1.331 -1.498,1.359 -1.498,2.146 -0.36,3.284 30.141,3.284 30.846,3.284 32.163,4.6 34.441,4.6 36.831,2.21 36.831,1.434 36.81,1.414 pad.34@36.791,1.414
el125: E1.86 pad.34@36.791,1.264 U1.AE5 | length 42.3
  metal 2 w0.012: E1.86@36.791,1.244 pad.34@36.791,1.264
  metal1 w0.005: U1.AE5@-1.47,1.191 -1.508,1.229 -1.508,2.15 -0.364,3.294 30.141,3.294 30.842,3.294 32.159,4.61 34.445,4.61 36.841,2.214 36.841,1.294 36.81,1.264 pad.34@36.791,1.264
el126: E1.109 pad.34@36.791,1.114 U1.AE6 | length 42.7
  metal 2 w0.012: E1.109@36.791,1.094 pad.34@36.791,1.114
  metal1 w0.005: U1.AE6@-1.47,1.051 -1.518,1.099 -1.518,2.154 -0.368,3.304 30.141,3.304 30.838,3.304 32.155,4.62 34.449,4.62 36.851,2.218 36.851,1.154 36.81,1.114 pad.34@36.791,1.114
el127: E1.132 pad.34@36.791,0.964 U1.AE7 | length 43
  metal 2 w0.012: E1.132@36.791,0.944 pad.34@36.791,0.964
  metal1 w0.005: U1.AE7@-1.47,0.911 -1.528,0.969 -1.528,2.158 -0.372,3.314 30.141,3.314 30.834,3.314 32.151,4.63 34.453,4.63 36.861,2.223 36.861,1.014 36.81,0.964 pad.34@36.791,0.964
el128: E1.139 pad.34@34.391,0.814 U1.D8 | length 35.4
  metal 2 w0.012: E1.139@34.391,0.794 pad.34@34.391,0.814
  metal1 w0.005: U1.D8@1.47,0.771 1.487,0.754 4.954,0.754 5.443,1.243 30.141,1.243 31.443,1.243 32.943,2.743 33.681,2.743 34.471,1.953 34.471,0.874 34.41,0.814 pad.34@34.391,0.814
el129: E1.161 pad.34@34.241,0.664 U1.D9 | length 35.3
  metal 2 w0.012: E1.161@34.241,0.644 pad.34@34.241,0.664
  metal1 w0.005: U1.D9@1.47,0.631 1.487,0.614 4.972,0.614 5.49,1.133 30.141,1.133 31.489,1.133 32.989,2.633 33.636,2.633 34.331,1.938 34.331,0.734 34.26,0.664 pad.34@34.241,0.664
el130: E1.44 pad.34@33.941,1.414 U1.D12 | length 34.1
  metal 2 w0.012: E1.44@33.941,1.394 pad.34@33.941,1.414
  metal1 w0.005: U1.D12@1.47,0.211 1.487,0.194 4.963,0.194 5.612,0.843 6.137,0.843 30.104,0.843 31.609,0.843 33.109,2.343 33.516,2.343 33.981,1.878 33.981,1.434 33.96,1.414 pad.34@33.941,1.414
el131: E1.66 pad.34@33.791,1.264 U1.D13 | length 34.1
  metal 2 w0.012: E1.66@33.791,1.244 pad.34@33.791,1.264
  metal1 w0.005: U1.D13@1.47,0.071 1.487,0.054 4.979,0.054 5.657,0.733 30.141,0.733 31.655,0.733 33.155,2.233 33.47,2.233 33.841,1.862 33.841,1.294 33.81,1.264 pad.34@33.791,1.264
el132: E1.116 pad.34@34.391,0.964 U1.E8 | length 35.3
  metal 2 w0.012: E1.116@34.391,0.944 pad.34@34.391,0.964
  metal1 w0.005: U1.E8@1.33,0.771 1.357,0.744 4.958,0.744 5.447,1.233 30.141,1.233 31.447,1.233 32.947,2.733 33.677,2.733 34.461,1.949 34.461,1.014 34.41,0.964 pad.34@34.391,0.964
el133: E1.138 pad.34@34.241,0.814 U1.E9 | length 35.3
  metal 2 w0.012: E1.138@34.241,0.794 pad.34@34.241,0.814
  metal1 w0.005: U1.E9@1.33,0.631 1.357,0.604 4.976,0.604 5.494,1.123 6.137,1.123 30.141,1.123 31.493,1.123 32.993,2.623 33.632,2.623 34.321,1.934 34.321,0.874 34.26,0.814 pad.34@34.241,0.814
el134: E1.22 pad.34@33.941,1.564 U1.E12 | length 34.1
  metal 2 w0.012: E1.22@33.941,1.544 pad.34@33.941,1.564
  metal1 w0.005: U1.E12@1.33,0.211 1.357,0.184 4.967,0.184 5.616,0.833 6.137,0.833 30.108,0.833 31.613,0.833 33.113,2.333 33.512,2.333 33.971,1.873 33.971,1.594 pad.34@33.941,1.564
el135: E1.43 pad.34@33.791,1.414 U1.E13 | length 34.1
  metal 2 w0.012: E1.43@33.791,1.394 pad.34@33.791,1.414
  metal1 w0.005: U1.E13@1.33,0.071 1.357,0.044 4.983,0.044 5.661,0.722 31.659,0.722 33.159,2.222 33.466,2.222 33.831,1.858 33.831,1.434 33.81,1.414 pad.34@33.791,1.414
el136: E1.93 pad.34@34.391,1.114 U1.F8 | length 35.3
  metal 2 w0.012: E1.93@34.391,1.094 pad.34@34.391,1.114
  metal1 w0.005: U1.F8@1.19,0.771 1.227,0.734 4.962,0.734 5.451,1.223 30.141,1.223 31.452,1.223 32.952,2.723 33.673,2.723 34.451,1.945 34.451,1.154 34.41,1.114 pad.34@34.391,1.114
el137: E1.115 pad.34@34.241,0.964 U1.F9 | length 35.3
  metal 2 w0.012: E1.115@34.241,0.944 pad.34@34.241,0.964
  metal1 w0.005: U1.F9@1.19,0.631 1.227,0.594 4.98,0.594 5.499,1.113 6.137,1.113 30.141,1.113 31.497,1.113 32.997,2.613 33.628,2.613 34.311,1.929 34.311,1.014 34.26,0.964 pad.34@34.241,0.964
el138: E1.183 pad.34@34.091,0.514 U1.F10 | length 35.6
  metal 2 w0.012: E1.183@34.091,0.494 pad.34@34.091,0.514
  metal1 w0.005: U1.F10@1.19,0.491 1.227,0.454 4.968,0.454 5.537,1.023 30.141,1.023 31.534,1.023 33.034,2.523 33.59,2.523 34.191,1.922 34.191,0.594 34.11,0.514 pad.34@34.091,0.514
el139: E1.251 pad.34@33.941,0.064 U1.F11 | length 35.9
  metal 2 w0.012: E1.251@33.941,0.044 pad.34@33.941,0.064
  metal1 w0.005: U1.F11@1.19,0.351 1.227,0.314 4.956,0.314 5.574,0.933 6.137,0.933 30.066,0.933 31.572,0.933 33.072,2.433 33.553,2.433 34.071,1.915 34.071,0.174 33.96,0.064 pad.34@33.941,0.064
el140: E1.2 pad.34@33.941,1.714 U1.F12 | length 34
  metal 2 w0.012: E1.2@33.941,1.694 pad.34@33.941,1.714
  metal1 w0.005: U1.F12@1.19,0.211 1.227,0.174 4.971,0.174 5.62,0.823 6.137,0.823 30.112,0.823 31.617,0.823 33.117,2.323 33.507,2.323 33.961,1.869 33.961,1.734 pad.34@33.941,1.714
